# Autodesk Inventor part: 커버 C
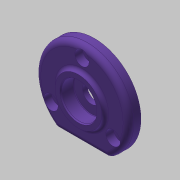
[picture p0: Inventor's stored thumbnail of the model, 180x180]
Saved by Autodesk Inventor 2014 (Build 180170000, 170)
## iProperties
Created: 2020-04
Part Number: 커버 C
Material: 알루미늄 6061
Document SubType Name: Modeling
Designer: mduedu
Density: 2.71 g/cm^3
Appearance: 보라색
Mass: 35.2365 g
Surface Area: 62.3737 cm^2
Volume: 13.0024 cm^3
Author: mduedu
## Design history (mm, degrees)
sketch "스케치1"
  geometry: C1 r 26 at (0, 0); 1 further point
  constraints: 1 centre point, 1 coincident
  dimensions: "d0" = 52 diameter of C1
extrude "돌출1" new body sketch "스케치1" distance "d1" = 7; taper "d2" = 0 deg
sketch "스케치2"
  geometry: L1 (-14.62, -21.5)-(14.62, -21.5); A1 r 26 centre (0, 0) between (-14.62, -21.5) and (14.62, -21.5) reference; 1 further point
  constraints: 2 end point, 2 point on circle, 1 horizontal
  dimensions: "d3" = 21.5 distance from line of L1 point (0, 0)
extrude "돌출2" cut sketch "스케치2" stored distance "d4" = 7; taper "d5" = 0 deg
sketch "스케치6"
  geometry: C1 r 13 at (0, 0); 1 further point
  constraints: 1 centre point, 1 coincident
  dimensions: "d29" = 26 diameter of C1
extrude "돌출5" join sketch "스케치6" distance "d30" = 2; taper "d31" = 0 deg
fillet "모깎기1" dims "d6" = 3
fillet "모깎기2" dims "d7" = 3
fillet "모깎기4" dims "d33" = 2
sketch "스케치3" dims "d8" = 40
  geometry: 3 further points
  constraints: 2 vertical alignment, 1 coincident, 2 other
hole "구멍1" sketch "스케치3" at (0, 20) diameter "d9" = 4.5; stored, may be unused: countersink angle "d13" = 90 deg, drill point angle "d15" = 118 deg; dims "d10" = 6, "d11" = 8, "d12" = 4.4, "d14" = 8
sketch "스케치4"
  geometry: C1 r 14 at (0, 0); 1 further point
  constraints: 1 centre point, 1 coincident
  dimensions: "d19" = 28 diameter of C1
extrude "돌출3" join sketch "스케치4" distance "d20" = 4; taper "d21" = 0 deg
sketch "스케치5"
  geometry: C1 r 12 at (0, 0); 1 further point
  constraints: 1 centre point, 1 coincident
  dimensions: "d22" = 24 diameter of C1
extrude "돌출4" cut sketch "스케치5" distance "d23" = 3; taper "d24" = 0 deg
fillet "모깎기3" dims "d25" = 3
chamfer "모따기1" distance "d26" = 0.5; stored, may be unused: second distance "d27" = 2, angle "d28" = 45 deg
sketch "스케치7"
  geometry: 2 further points
  constraints: 1 coincident
hole "구멍2" sketch "스케치7" at (0, 0) diameter "d34" = 10; stored, may be unused: countersink angle "d38" = 90 deg, drill point angle "d40" = 118 deg; dims "d35" = 6, "d36" = 20, "d37" = 7.3, "d39" = 8
fillet "모깎기5" dims "d41" = 0.3
chamfer "모따기2" distance "d42" = 0.7; stored, may be unused: second distance "d43" = 2, angle "d44" = 30 deg
node "솔리드1"
pattern_circular "원형 패턴1" dims angle "d17" = 360 deg
node "투영된 루프1"
